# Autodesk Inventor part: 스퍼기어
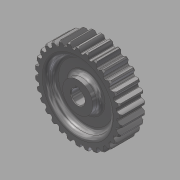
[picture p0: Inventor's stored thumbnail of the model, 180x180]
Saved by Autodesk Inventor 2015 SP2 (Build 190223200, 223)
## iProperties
Created: 2015-11
Part Number: 스퍼기어
Material: 강철, 탄소
Document SubType Name: Modeling
Designer: mduedu
Density: 1 g/cm^3
Appearance: 반광택
Author: mduedu
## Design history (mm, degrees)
sketch "스케치1"
  geometry: C1 r 28.75 at (0, 0); 1 further point
  constraints: 1 centre point, 1 coincident
  dimensions: "d0" = 57.5 diameter of C1
extrude "돌출1" new body sketch "스케치1" stored distance "d2" = 18; taper "d3" = 0 deg
sketch "스케치2" dims "d4" = 60
  geometry: L1 (0, 0)-(0, 32); L2 (-32, 0)-(32, 0); L3 (-2.07, 0)-(-2.07, 40.614); L4 (-2.07, 40.614)-(-1.57, 40.614); L5 (-1.57, 40.614)-(-1.57, 0); L6 (-0.57, 0)-(-0.57, 40.614); L7 (-0.57, 40.614)-(0, 40.614); L8 (0, 40.614)-(0, 0); A1 r 32 centre (0, 0) between (0.57, 31.995) and (-0.57, 31.995); A2 r 21.436 centre (18.143, 21.54) between (-0.57, 31.995) and (-2.07, 28.675); A3 r 21.436 centre (-18.143, 21.54) between (2.07, 28.675) and (0.57, 31.995); A4 r 32 centre (0, 0) between (32, 0) and (0.57, 31.995); A5 r 32 centre (0, 0) between (-0.57, 31.995) and (32, 0); A6 r 28.75 centre (0, 0) between (2.07, 28.675) and (-2.07, 28.675); 4 further points
  constraints: 17 point on circle, 16 end point, 6 centre point, 6 point on line, 5 perpendicular, 4 coincident, 3 symmetric about line, 2 collinear, 1 midpoint, 1 parallel, 1 vertical, 6 other
  dimensions: "d6" = 64 diameter of A1; "d7" = 0.5 distance between parallel lines of L5 L3; "d8" = 1 distance between parallel lines of L6 L5; "d9" = 40.61409 distance of L4.end L5.end; "d10" = 1.57 distance between parallel lines of L8 L5
extrude "돌출2" join sketch "스케치2" stored distance "d11" = 18; taper "d12" = 0 deg
fillet "모깎기1" dims "d16" = 0.5
chamfer "모따기3" distance "d26" = 1; stored, may be unused: second distance "d27" = 2, angle "d28" = 45 deg
sketch "스케치3"
  geometry: C1 r 23 at (0, 0); C2 r 11 at (0, 0); 1 further point
  constraints: 2 centre point, 2 coincident
  dimensions: "d32" = 46 diameter of C1; "d33" = 22 diameter of C2
extrude "돌출3" cut sketch "스케치3" distance "d34" = 6; taper "d35" = 0 deg
fillet "모깎기2" dims "d36" = 3
hole "구멍1" diameter "d39" = 10; stored, may be unused: countersink angle "d43" = 90 deg, drill point angle "d45" = 118 deg; dims "d37" = 10, "d38" = 10, "d40" = 6, "d41" = 4, "d42" = 2, "d44" = 8
sketch "스케치5"
  geometry: L1 (-1.5, 0)-(1.5, 0); L2 (1.5, 0)-(1.5, 6.4); L3 (1.5, 6.4)-(-1.5, 6.4); L4 (-1.5, 6.4)-(-1.5, 0); 2 further points
  constraints: 8 end point, 2 parallel, 1 coincident, 1 horizontal, 1 midpoint, 1 perpendicular
  dimensions: "d46" = 3 distance of L2.end L3.end; "d48" = 6.4 distance of L1.end L2.end
extrude "돌출4" cut sketch "스케치5" stored distance "d49" = 6; taper "d50" = 0 deg
chamfer "모따기4" distance "d51" = 0.5; stored, may be unused: second distance "d52" = 2, angle "d53" = 45 deg
node "솔리드1"
pattern_circular "원형 패턴3" dims "d30" = 360 deg
mirror "대칭1"
